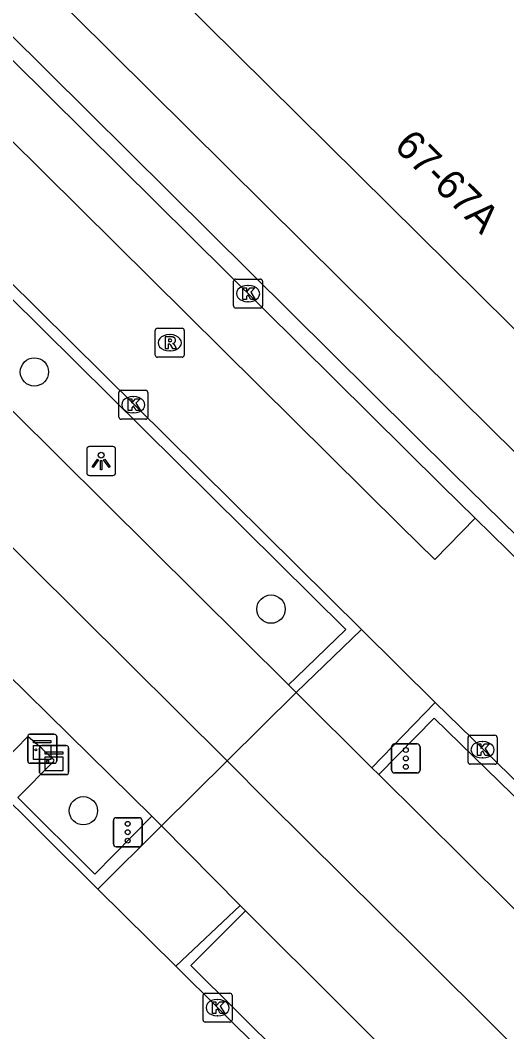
# Model space of a CAD drawing. Extents: x 159489 to 160304, y 383826 to 384530.
# Drawn here: x 160112.93 to 160129.73, y 384082.98 to 384117.9 of the extents above; entities that cross this region are included whole.
import ezdxf

# ---------------------------------------------------------------- set-up
doc = ezdxf.new("R2010")
doc.units = 0
for name, color, linetype in [('IMGEO_Berm_open', 7, 'Continuous'), ('IMGEO_Boom', 7, 'Continuous'), ('IMGEO_Kast', 7, 'Continuous'), ('IMGEO_Kolk', 7, 'Continuous'), ('IMGEO_Lichtpunt', 7, 'Continuous'), ('IMGEO_OVBaan_gesloten', 7, 'Continuous'), ('IMGEO_Pand', 7, 'Continuous'), ('IMGEO_Pand_nummerreeks', 7, 'Continuous'), ('IMGEO_Rijbaan_lokaal_gesloten', 7, 'Continuous'), ('IMGEO_Rioolput', 7, 'Continuous'), ('IMGEO_Verkeersregelinstallatiepaal', 7, 'Continuous'), ('IMGEO_Voetpad_open', 7, 'Continuous')]:
    doc.layers.add(name, color=color, linetype=linetype)

msp = doc.modelspace()

# ---------------------------------------------------------------- linework, layer by layer
at = {"layer": 'IMGEO_Berm_open'}
for points in [[(160077.959, 384143.62), (160082.602, 384138.728), (160085.974, 384135.143), (160089.551, 384131.422), (160104.378, 384116.447), (160124.176, 384096.867), (160122.466, 384095.227), (160122.2, 384094.958)], [(160125.311, 384091.863), (160127.226, 384093.803), (160139.35, 384081.995)], [(160117.476, 384090.421), (160115.511, 384088.422), (160112.85, 384091.065)], [(160128.398, 384075.765), (160118.819, 384085.275), (160120.706, 384087.162)]]:
    msp.add_lwpolyline(points, dxfattribs=at)
at = {"layer": 'IMGEO_Boom'}
for centre in [(160113.424, 384105.757), (160121.592, 384097.57), (160115.114, 384090.611)]:
    msp.add_circle(centre, 0.489, dxfattribs=at)
at = {"layer": 'IMGEO_Kast'}
for p, q in [((160113.193, 384092.326), (160113.193, 384093.167)), ((160113.193, 384093.167), (160113.193, 384092.326)), ((160113.268, 384093.251), (160114.109, 384093.251)), ((160114.109, 384093.251), (160113.268, 384093.251)), ((160114.193, 384093.176), (160114.193, 384092.335)), ((160114.193, 384092.335), (160114.193, 384093.176)), ((160113.604, 384091.936), (160113.604, 384092.777)), ((160113.604, 384092.777), (160113.604, 384091.936)), ((160113.679, 384092.861), (160114.52, 384092.861)), ((160114.52, 384092.861), (160113.679, 384092.861)), ((160114.604, 384092.786), (160114.604, 384091.945)), ((160114.604, 384091.945), (160114.604, 384092.786)), ((160114.118, 384092.251), (160113.277, 384092.251)), ((160113.277, 384092.251), (160114.118, 384092.251)), ((160114.529, 384091.861), (160113.688, 384091.861)), ((160113.688, 384091.861), (160114.529, 384091.861))]:
    msp.add_line(p, q, dxfattribs=at)
for points in [[(160113.388, 384093.041), (160113.988, 384093.041), (160113.988, 384092.956), (160113.388, 384092.956), (160113.388, 384093.041)], [(160113.388, 384092.866), (160113.988, 384092.866), (160113.988, 384092.377), (160113.388, 384092.377), (160113.388, 384092.866)], [(160113.799, 384092.651), (160114.399, 384092.651), (160114.399, 384092.566), (160113.799, 384092.566), (160113.799, 384092.651)], [(160113.799, 384092.476), (160114.399, 384092.476), (160114.399, 384091.987), (160113.799, 384091.987), (160113.799, 384092.476)]]:
    msp.add_lwpolyline(points, dxfattribs=at)
for centre in [(160113.472, 384092.715), (160113.883, 384092.325)]:
    msp.add_circle(centre, 0.0377, dxfattribs=at)
for centre, start, end in [((160113.271, 384093.173), 92.4484, 184.2845), ((160113.271, 384093.173), 92.4484, 184.2845), ((160114.115, 384093.173), 2.4484, 94.2845), ((160114.115, 384093.173), 2.4484, 94.2845), ((160113.682, 384092.783), 92.4484, 184.2845), ((160113.682, 384092.783), 92.4484, 184.2845), ((160114.526, 384092.783), 2.4484, 94.2845), ((160114.526, 384092.783), 2.4484, 94.2845), ((160113.271, 384092.329), 182.4484, 274.2845), ((160113.271, 384092.329), 182.4484, 274.2845), ((160114.115, 384092.329), 272.4484, 4.2845), ((160114.115, 384092.329), 272.4484, 4.2845), ((160113.682, 384091.939), 182.4484, 274.2845), ((160113.682, 384091.939), 182.4484, 274.2845), ((160114.526, 384091.939), 272.4484, 4.2845), ((160114.526, 384091.939), 272.4484, 4.2845)]:
    msp.add_arc(centre, 0.0779, start, end, dxfattribs=at)
at = {"layer": 'IMGEO_Kolk'}
for p, q in [((160120.298, 384108.033), (160120.298, 384108.885)), ((160120.373, 384108.959), (160121.225, 384108.959)), ((160121.299, 384108.885), (160121.299, 384108.033)), ((160120.786, 384108.739), (160120.811, 384108.739)), ((160120.809, 384108.179), (160120.784, 384108.179)), ((160121.225, 384107.959), (160120.373, 384107.959)), ((160116.338, 384104.199), (160116.338, 384105.051)), ((160116.413, 384105.125), (160117.265, 384105.125)), ((160117.339, 384105.051), (160117.339, 384104.199)), ((160116.826, 384104.905), (160116.851, 384104.905)), ((160116.849, 384104.345), (160116.824, 384104.345)), ((160117.265, 384104.125), (160116.413, 384104.125)), ((160128.395, 384092.291), (160128.395, 384093.143)), ((160128.47, 384093.217), (160129.322, 384093.217)), ((160129.396, 384093.143), (160129.396, 384092.291)), ((160128.883, 384092.997), (160128.908, 384092.997)), ((160128.906, 384092.437), (160128.881, 384092.437)), ((160129.322, 384092.217), (160128.47, 384092.217)), ((160119.247, 384083.39), (160119.247, 384084.242)), ((160119.322, 384084.316), (160120.174, 384084.316)), ((160119.735, 384084.096), (160119.76, 384084.096)), ((160120.248, 384084.242), (160120.248, 384083.39)), ((160119.758, 384083.536), (160119.733, 384083.536)), ((160120.174, 384083.316), (160119.322, 384083.316))]:
    msp.add_line(p, q, dxfattribs=at)
for points in [[(160120.298, 384108.033), (160120.298, 384108.885)], [(160120.373, 384108.959), (160121.225, 384108.959)], [(160121.299, 384108.885), (160121.299, 384108.033)], [(160120.619, 384108.659), (160120.742, 384108.659), (160120.742, 384108.508), (160120.872, 384108.659), (160121.036, 384108.659), (160120.89, 384108.508), (160121.043, 384108.259), (160120.891, 384108.259), (160120.806, 384108.423), (160120.742, 384108.356), (160120.742, 384108.259), (160120.619, 384108.259), (160120.619, 384108.659)], [(160121.225, 384107.959), (160120.373, 384107.959)], [(160116.338, 384104.199), (160116.338, 384105.051)], [(160116.413, 384105.125), (160117.265, 384105.125)], [(160117.339, 384105.051), (160117.339, 384104.199)], [(160116.659, 384104.825), (160116.782, 384104.825), (160116.782, 384104.674), (160116.912, 384104.825), (160117.076, 384104.825), (160116.93, 384104.674), (160117.083, 384104.425), (160116.931, 384104.425), (160116.846, 384104.589), (160116.782, 384104.522), (160116.782, 384104.425), (160116.659, 384104.425), (160116.659, 384104.825)], [(160117.265, 384104.125), (160116.413, 384104.125)], [(160128.395, 384092.291), (160128.395, 384093.143)], [(160128.47, 384093.217), (160129.322, 384093.217)], [(160129.396, 384093.143), (160129.396, 384092.291)], [(160128.716, 384092.917), (160128.839, 384092.917), (160128.839, 384092.766), (160128.969, 384092.917), (160129.133, 384092.917), (160128.987, 384092.766), (160129.14, 384092.517), (160128.988, 384092.517), (160128.903, 384092.681), (160128.839, 384092.614), (160128.839, 384092.517), (160128.716, 384092.517), (160128.716, 384092.917)], [(160129.322, 384092.217), (160128.47, 384092.217)], [(160119.247, 384083.39), (160119.247, 384084.242)], [(160119.322, 384084.316), (160120.174, 384084.316)], [(160120.248, 384084.242), (160120.248, 384083.39)], [(160119.568, 384084.016), (160119.691, 384084.016), (160119.691, 384083.865), (160119.821, 384084.016), (160119.985, 384084.016), (160119.839, 384083.865), (160119.992, 384083.616), (160119.84, 384083.616), (160119.755, 384083.78), (160119.691, 384083.713), (160119.691, 384083.616), (160119.568, 384083.616), (160119.568, 384084.016)], [(160120.174, 384083.316), (160119.322, 384083.316)]]:
    msp.add_lwpolyline(points, dxfattribs=at)
for centre, start, end in [((160120.375, 384108.883), 91.552, 178.448), ((160120.375, 384108.883), 91.552, 178.448), ((160121.223, 384108.883), 1.552, 88.448), ((160121.223, 384108.883), 1.552, 88.448), ((160120.375, 384108.035), 181.552, 268.448), ((160120.375, 384108.035), 181.552, 268.448), ((160121.223, 384108.035), 271.552, 358.448), ((160121.223, 384108.035), 271.552, 358.448), ((160116.415, 384105.049), 91.552, 178.448), ((160116.415, 384105.049), 91.552, 178.448), ((160117.263, 384105.049), 1.552, 88.448), ((160117.263, 384105.049), 1.552, 88.448), ((160116.415, 384104.201), 181.552, 268.448), ((160116.415, 384104.201), 181.552, 268.448), ((160117.263, 384104.201), 271.552, 358.448), ((160117.263, 384104.201), 271.552, 358.448), ((160128.472, 384093.141), 91.552, 178.448), ((160128.472, 384093.141), 91.552, 178.448), ((160129.32, 384093.141), 1.552, 88.448), ((160129.32, 384093.141), 1.552, 88.448), ((160128.472, 384092.293), 181.552, 268.448), ((160128.472, 384092.293), 181.552, 268.448), ((160129.32, 384092.293), 271.552, 358.448), ((160129.32, 384092.293), 271.552, 358.448), ((160119.324, 384084.24), 91.552, 178.448), ((160119.324, 384084.24), 91.552, 178.448), ((160120.172, 384084.24), 1.552, 88.448), ((160120.172, 384084.24), 1.552, 88.448), ((160119.324, 384083.392), 181.552, 268.448), ((160119.324, 384083.392), 181.552, 268.448), ((160120.172, 384083.392), 271.552, 358.448), ((160120.172, 384083.392), 271.552, 358.448)]:
    msp.add_arc(centre, 0.0765, start, end, dxfattribs=at)
for centre, major_axis, ratio, start_param, end_param in [((160120.785, 384108.459), (-0.387, 0.002), 0.722429, 4.712389, 7.853982), ((160120.81, 384108.459), (-0.39, 0.002), 0.717154, 1.570796, 4.712389), ((160116.825, 384104.625), (-0.387, 0.002), 0.722429, 4.712389, 7.853982), ((160116.85, 384104.625), (-0.39, 0.002), 0.717154, 1.570796, 4.712389), ((160128.882, 384092.717), (-0.387, 0.002), 0.722429, 4.712389, 7.853982), ((160128.907, 384092.717), (-0.39, 0.002), 0.717154, 1.570796, 4.712389), ((160119.734, 384083.816), (-0.387, 0.002), 0.722429, 4.712389, 7.853982), ((160119.759, 384083.816), (-0.39, 0.002), 0.717154, 1.570796, 4.712389)]:
    msp.add_ellipse(centre, major_axis=major_axis, ratio=ratio, start_param=start_param, end_param=end_param, dxfattribs=at)
at = {"layer": 'IMGEO_Lichtpunt'}
for p, q in [((160115.228, 384103.086), (160115.228, 384102.279)), ((160115.228, 384103.086), (160115.228, 384102.279)), ((160116.13, 384103.181), (160115.322, 384103.181)), ((160116.13, 384103.181), (160115.322, 384103.181)), ((160116.224, 384102.279), (160116.224, 384103.086)), ((160116.224, 384102.279), (160116.224, 384103.086)), ((160115.322, 384102.185), (160116.13, 384102.185)), ((160115.322, 384102.185), (160116.13, 384102.185))]:
    msp.add_line(p, q, dxfattribs=at)
for points in [[(160115.602, 384102.75), (160115.641, 384102.722), (160115.453, 384102.46), (160115.415, 384102.487), (160115.602, 384102.75)], [(160115.704, 384102.702), (160115.751, 384102.702), (160115.751, 384102.38), (160115.704, 384102.38), (160115.704, 384102.702)], [(160115.814, 384102.722), (160115.852, 384102.749), (160116.039, 384102.487), (160116, 384102.459), (160115.814, 384102.722)]]:
    msp.add_lwpolyline(points, dxfattribs=at)
msp.add_circle((160115.727, 384102.884), 0.0994, dxfattribs=at)
for centre, start, end in [((160115.322, 384103.086), 90, 180), ((160115.322, 384103.086), 90, 180), ((160116.13, 384103.086), 0, 90), ((160116.13, 384103.086), 0, 90), ((160115.322, 384102.279), 180, 270), ((160115.322, 384102.279), 180, 270), ((160116.13, 384102.279), 270, 0), ((160116.13, 384102.279), 270, 360)]:
    msp.add_arc(centre, 0.0946, start, end, dxfattribs=at)
at = {"layer": 'IMGEO_OVBaan_gesloten'}
for points in [[(160069.289, 384135.267), (160073.24, 384131.352), (160075.482, 384129.271), (160101.702, 384105.934), (160117.476, 384090.421)], [(160122.2, 384094.958), (160103.171, 384113.83)], [(160104.77, 384107.525), (160120.074, 384092.332)], [(160122.462, 384094.698), (160122.2, 384094.958)], [(160120.074, 384092.332), (160122.462, 384094.698)], [(160125.075, 384092.097), (160122.462, 384094.698)], [(160120.074, 384092.332), (160117.812, 384090.09)], [(160180.322, 384037.159), (160176.612, 384040.154), (160173.526, 384042.635), (160170.286, 384045.296), (160167.466, 384047.665), (160161.694, 384052.642), (160158.499, 384055.447), (160149.532, 384063.51), (160140.973, 384071.696), (160132.364, 384080.101), (160126.671, 384085.78), (160121.497, 384090.909), (160120.074, 384092.332)], [(160125.075, 384092.097), (160125.311, 384091.863)], [(160125.311, 384091.863), (160138.676, 384078.616), (160148.264, 384069.294)], [(160117.476, 384090.421), (160117.812, 384090.09)], [(160120.53, 384087.34), (160117.812, 384090.09)], [(160120.706, 384087.162), (160120.53, 384087.34)], [(160120.706, 384087.162), (160130.716, 384077.192), (160143.29, 384064.966), (160151.014, 384057.786), (160158.099, 384051.509), (160167.768, 384043.203)]]:
    msp.add_lwpolyline(points, dxfattribs=at)
at = {"layer": 'IMGEO_Pand'}
msp.add_lwpolyline([(160170.652, 384124.06), (160149.144, 384150.025), (160115.174, 384121.901), (160139.273, 384098.067), (160170.652, 384124.06)], dxfattribs=at)
at = {"layer": 'IMGEO_Rijbaan_lokaal_gesloten'}
for points in [[(160055.797, 384168.686), (160066.449, 384156.825), (160076.823, 384145.424), (160086.248, 384135.404), (160089.822, 384131.686), (160104.646, 384116.715), (160124.719, 384096.863)], [(160115.618, 384087.91), (160078.271, 384125.002), (160074.885, 384128.567), (160057.461, 384147.627), (160051.82, 384153.954), (160046.275, 384160.409)], [(160128.637, 384100.713), (160127.245, 384099.289), (160126.087, 384100.422), (160107.564, 384118.761), (160097.127, 384129.22), (160092.588, 384133.903), (160094.018, 384135.288)], [(160131.457, 384097.954), (160128.637, 384100.713)], [(160124.719, 384096.863), (160127.256, 384094.343)], [(160170.706, 384053.56), (160165.391, 384058.144), (160156.588, 384065.977), (160150.41, 384071.823), (160127.256, 384094.343)], [(160115.618, 384087.91), (160118.31, 384085.245)], [(160118.31, 384085.245), (160133.504, 384070.172), (160142.019, 384061.981), (160148.836, 384055.647), (160158.264, 384047.279), (160162.524, 384043.624)]]:
    msp.add_lwpolyline(points, dxfattribs=at)
at = {"layer": 'IMGEO_Rioolput'}
for p, q in [((160117.596, 384106.339), (160117.596, 384107.191)), ((160117.671, 384107.265), (160118.523, 384107.265)), ((160118.597, 384107.191), (160118.597, 384106.339)), ((160118.084, 384107.045), (160118.109, 384107.045)), ((160118.107, 384106.485), (160118.082, 384106.485)), ((160118.523, 384106.265), (160117.671, 384106.265))]:
    msp.add_line(p, q, dxfattribs=at)
for points in [[(160117.596, 384106.339), (160117.596, 384107.191)], [(160117.671, 384107.265), (160118.523, 384107.265)], [(160118.597, 384107.191), (160118.597, 384106.339)], [(160118.185, 384106.963), (160117.933, 384106.965), (160117.933, 384106.565)], [(160118.111, 384106.884), (160118.057, 384106.884), (160118.057, 384106.803)], [(160118.057, 384106.803), (160118.109, 384106.803)], [(160117.933, 384106.565), (160118.057, 384106.565), (160118.057, 384106.727), (160118.068, 384106.727)], [(160118.115, 384106.698), (160118.186, 384106.565), (160118.326, 384106.565), (160118.261, 384106.691)], [(160118.523, 384106.265), (160117.671, 384106.265)]]:
    msp.add_lwpolyline(points, dxfattribs=at)
for centre, radius, start, end in [((160117.673, 384107.189), 0.0765, 91.552, 178.448), ((160117.673, 384107.189), 0.0765, 91.552, 178.448), ((160118.521, 384107.189), 0.0765, 1.552, 88.448), ((160118.521, 384107.189), 0.0765, 1.552, 88.448), ((160118.093, 384106.992), 0.19, 274.7715, 282.9687), ((160118.117, 384106.788), 0.0964, 77.0061, 93.1865), ((160118.131, 384106.845), 0.0378, 276.6634, 79.6772), ((160118.184, 384106.853), 0.109, 350.3612, 89.416), ((160118.182, 384106.853), 0.112, 277.5842, 350.9817), ((160118.166, 384106.638), 0.108, 29.5134, 73.7905), ((160118.067, 384106.674), 0.0533, 26.0293, 88.6989), ((160117.673, 384106.341), 0.0765, 181.552, 268.448), ((160117.673, 384106.341), 0.0765, 181.552, 268.448), ((160118.521, 384106.341), 0.0765, 271.552, 358.448), ((160118.521, 384106.341), 0.0765, 271.552, 358.448)]:
    msp.add_arc(centre, radius, start, end, dxfattribs=at)
for centre, major_axis, ratio, start_param, end_param in [((160118.083, 384106.765), (-0.387, 0.002), 0.722429, 4.712389, 7.853982), ((160118.108, 384106.765), (-0.39, 0.002), 0.717154, 1.570796, 4.712389)]:
    msp.add_ellipse(centre, major_axis=major_axis, ratio=ratio, start_param=start_param, end_param=end_param, dxfattribs=at)
at = {"layer": 'IMGEO_Verkeersregelinstallatiepaal'}
for p, q in [((160125.751, 384092.017), (160125.751, 384092.817)), ((160125.751, 384092.817), (160125.751, 384092.017)), ((160125.851, 384092.917), (160126.641, 384092.917)), ((160126.641, 384092.917), (160125.851, 384092.917)), ((160126.741, 384092.817), (160126.741, 384092.017)), ((160126.741, 384092.017), (160126.741, 384092.817)), ((160126.641, 384091.917), (160125.851, 384091.917)), ((160125.851, 384091.917), (160126.641, 384091.917)), ((160116.248, 384090.37), (160117.038, 384090.37)), ((160117.038, 384090.37), (160116.248, 384090.37)), ((160116.148, 384089.47), (160116.148, 384090.27)), ((160116.148, 384090.27), (160116.148, 384089.47)), ((160117.138, 384090.27), (160117.138, 384089.47)), ((160117.138, 384089.47), (160117.138, 384090.27)), ((160117.038, 384089.37), (160116.248, 384089.37)), ((160116.248, 384089.37), (160117.038, 384089.37))]:
    msp.add_line(p, q, dxfattribs=at)
for centre in [(160126.246, 384092.707), (160126.246, 384092.417), (160126.246, 384092.127), (160116.643, 384090.16), (160116.643, 384089.87), (160116.643, 384089.58)]:
    msp.add_circle(centre, 0.085, dxfattribs=at)
for centre, start, end in [((160125.851, 384092.817), 90, 180), ((160125.851, 384092.817), 90, 180), ((160126.641, 384092.817), 0, 90), ((160126.641, 384092.817), 360, 90), ((160125.851, 384092.017), 180, 270), ((160125.851, 384092.017), 180, 270), ((160126.641, 384092.017), 270, 0), ((160126.641, 384092.017), 270, 0), ((160116.248, 384090.27), 90, 180), ((160116.248, 384090.27), 90, 180), ((160117.038, 384090.27), 0, 90), ((160117.038, 384090.27), 360, 90), ((160116.248, 384089.47), 180, 270), ((160116.248, 384089.47), 180, 270), ((160117.038, 384089.47), 270, 0), ((160117.038, 384089.47), 270, 0)]:
    msp.add_arc(centre, 0.1, start, end, dxfattribs=at)
at = {"layer": 'IMGEO_Voetpad_open'}
for points in [[(160050.34, 384187.958), (160051.553, 384186.494), (160055.185, 384182.183), (160055.979, 384181.24), (160057.954, 384178.895), (160063.061, 384172.832), (160065.382, 384170.193), (160066.214, 384169.246), (160072.272, 384162.355), (160075.872, 384158.402), (160076.696, 384157.497), (160082.448, 384151.179), (160091.223, 384141.843), (160105.53, 384127.244), (160129.28, 384103.698), (160141.431, 384091.785), (160146.087, 384087.221), (160154.183, 384079.487), (160154.902, 384078.8), (160161.156, 384072.825), (160168.424, 384066.164), (160174.496, 384060.831), (160173.165, 384059.326)], [(160173.165, 384059.326), (160167.091, 384064.648), (160161.015, 384070.183), (160146.171, 384084.356), (160127.88, 384102.246), (160104.079, 384125.847), (160094.817, 384135.246), (160084.845, 384145.686), (160074.003, 384157.433), (160066.213, 384166.161), (160061.626, 384171.427), (160049.101, 384186.313), (160048.804, 384186.671)], [(160094.018, 384135.288), (160098.547, 384130.616), (160108.969, 384120.172), (160127.484, 384101.841), (160128.637, 384100.713)], [(160122.462, 384094.698), (160124.719, 384096.863)], [(160127.256, 384094.343), (160125.075, 384092.097)], [(160112.85, 384091.065), (160114.08, 384092.315), (160114.104, 384092.361), (160113.693, 384092.751), (160113.2, 384093.18), (160111.975, 384091.934)], [(160117.812, 384090.09), (160115.618, 384087.91)], [(160120.53, 384087.34), (160118.31, 384085.245)]]:
    msp.add_lwpolyline(points, dxfattribs=at)

# ---------------------------------------------------------------- texts
at = {"layer": 'IMGEO_Pand_nummerreeks'}
msp.add_text('67-67A', height=1, rotation=315.315, dxfattribs=at).set_placement((160125.803, 384113.499))

doc.saveas('drawing.dxf')
